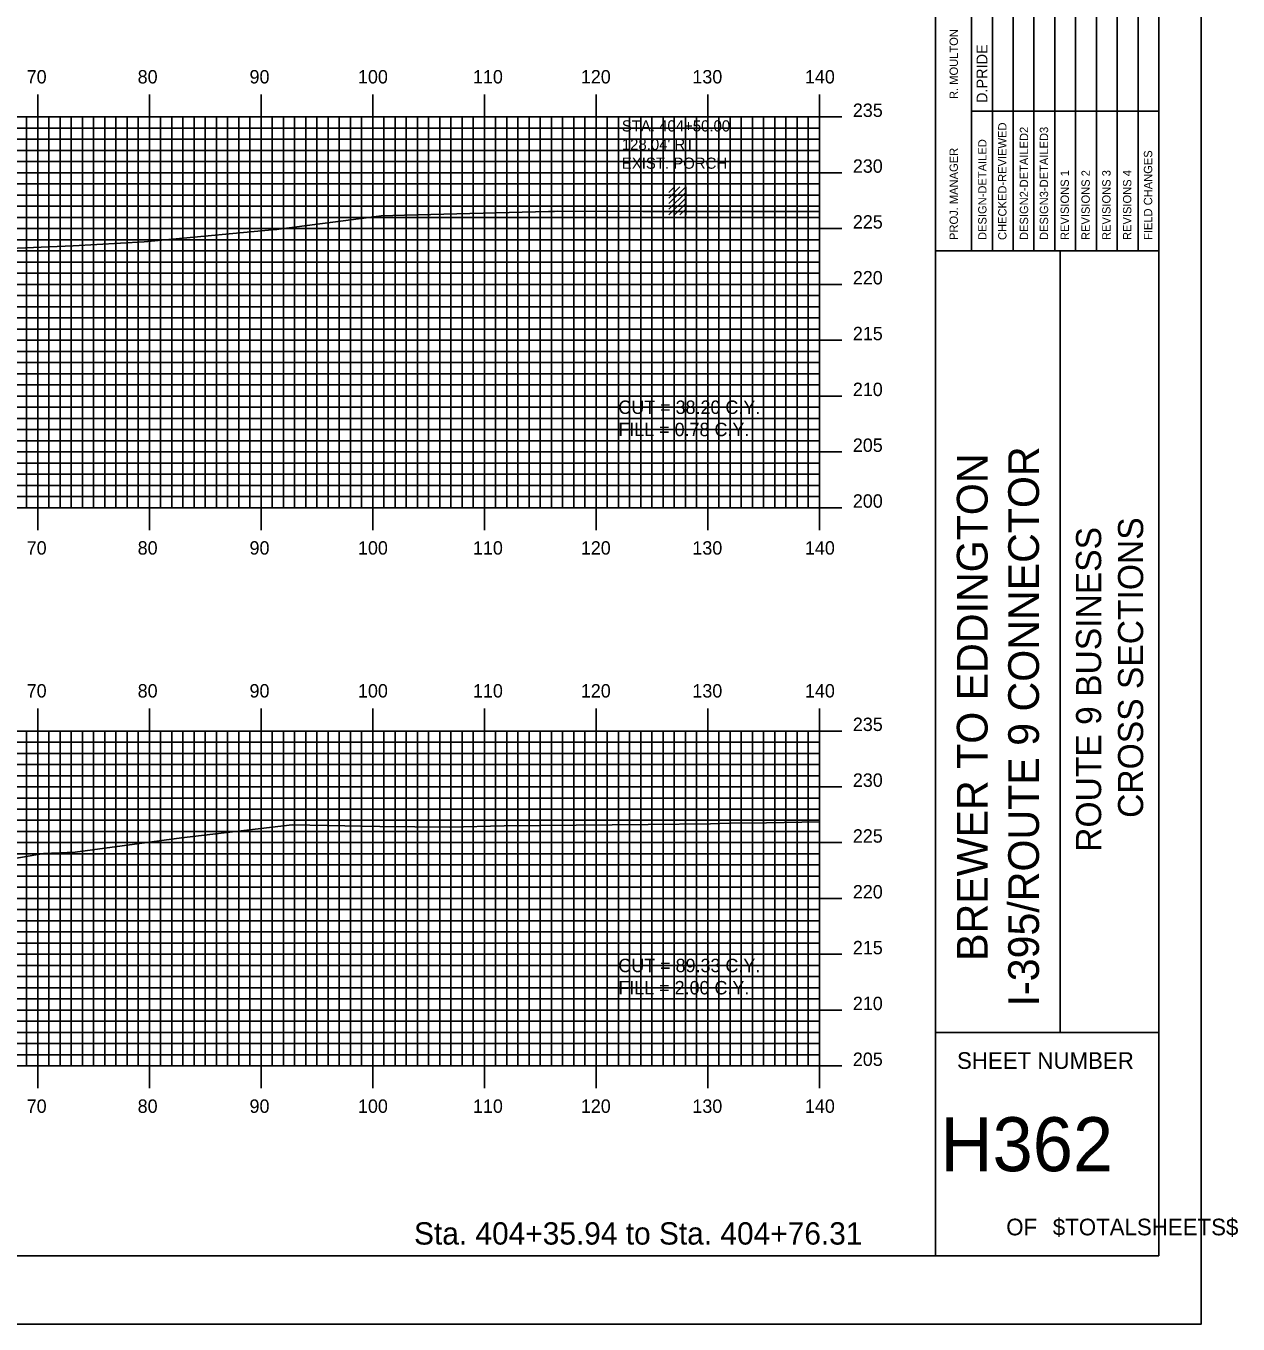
# Model space of a CAD drawing. Extents: x 851348 to 851692, y 364785 to 365005.
# Drawn here: x 851583.1 to 851691.7, y 364785.1 to 364901.4 of the extents above; entities that cross this region are included whole.
import ezdxf

# ---------------------------------------------------------------- set-up
doc = ezdxf.new("R2010")
doc.units = 0
for name, color, linetype in [('BORDER', 7, 'Continuous'), ('D_Text_Monospaced', 7, 'Continuous'), ('D_Text_Standard', 7, 'Continuous'), ('H_V ANNOTATION', 7, 'Continuous'), ('M_Buildings_Attachments', 7, 'Continuous'), ('MAJOR', 7, 'Continuous'), ('MINOR', 7, 'Continuous'), ('PLOT BOUNDARY', 7, 'Continuous'), ('S_Roadway_Centerline', 7, 'Continuous')]:
    doc.layers.add(name, color=color, linetype=linetype)

msp = doc.modelspace()

# ---------------------------------------------------------------- linework, layer by layer
at = {"layer": 'BORDER'}
for p, q in [((851664.59, 364791.23), (851664.59, 365001.23)), ((851664.59, 364881.24), (851684.59, 364881.24)), ((851675.77, 364811.24), (851675.77, 364881.24)), ((851664.59, 364811.24), (851684.59, 364811.24))]:
    msp.add_line(p, q, dxfattribs=at)
msp.add_lwpolyline([(851364.59, 364791.23), (851684.59, 364791.23), (851684.59, 365001.23), (851364.59, 365001.23)], close=True, dxfattribs=at)
for points in [[(851669.69, 364881.24), (851669.69, 364916.24)], [(851671.55, 364916.24), (851671.55, 364881.24)], [(851673.41, 364881.24), (851673.41, 364916.24)], [(851675.28, 364881.24), (851675.28, 364916.24)], [(851677.14, 364881.24), (851677.14, 364916.24)], [(851679, 364881.24), (851679, 364916.24)], [(851680.87, 364881.24), (851680.87, 364916.24)], [(851682.73, 364881.24), (851682.73, 364916.24)], [(851667.82, 364881.24), (851667.82, 364914.83)], [(851667.82, 364893.74), (851684.59, 364893.74)]]:
    msp.add_lwpolyline(points, dxfattribs=at)
at = {"layer": 'M_Buildings_Attachments'}
for p, q in [((851640.72, 364885.47), (851642.23, 364886.98)), ((851640.72, 364885.96), (851641.71, 364886.98)), ((851640.72, 364886.45), (851641.22, 364886.98)), ((851642.23, 364884.45), (851642.23, 364886.98)), ((851640.72, 364884.98), (851642.23, 364886.45)), ((851640.72, 364884.45), (851642.23, 364885.96)), ((851641.22, 364884.45), (851642.23, 364885.47)), ((851641.71, 364884.45), (851642.23, 364884.98))]:
    msp.add_line(p, q, dxfattribs=at)
at = {"layer": 'MAJOR'}
for p, q in [((851584.19, 364895.24), (851584.19, 364893.23)), ((851594.19, 364895.24), (851594.19, 364893.23)), ((851604.19, 364895.24), (851604.19, 364893.23)), ((851614.19, 364895.24), (851614.19, 364893.23)), ((851624.19, 364895.24), (851624.19, 364893.23)), ((851634.19, 364895.24), (851634.19, 364893.23)), ((851644.19, 364895.24), (851644.19, 364893.23)), ((851654.19, 364895.24), (851654.19, 364893.23)), ((851374.19, 364893.23), (851654.19, 364893.23)), ((851374.19, 364893.23), (851654.19, 364893.23)), ((851584.19, 364858.23), (851584.19, 364893.23)), ((851594.19, 364858.23), (851594.19, 364893.23)), ((851604.19, 364858.23), (851604.19, 364893.23)), ((851614.19, 364858.23), (851614.19, 364893.23)), ((851624.19, 364858.23), (851624.19, 364893.23)), ((851634.19, 364858.23), (851634.19, 364893.23)), ((851644.19, 364858.23), (851644.19, 364893.23)), ((851656.2, 364893.23), (851652.19, 364893.23)), ((851654.19, 364858.23), (851654.19, 364893.23)), ((851654.19, 364858.23), (851654.19, 364893.23)), ((851374.19, 364888.23), (851654.19, 364888.23)), ((851656.2, 364888.23), (851652.19, 364888.23)), ((851374.19, 364883.23), (851654.19, 364883.23)), ((851656.2, 364883.23), (851652.19, 364883.23)), ((851374.19, 364878.23), (851654.19, 364878.23)), ((851656.2, 364878.23), (851652.19, 364878.23)), ((851374.19, 364873.23), (851654.19, 364873.23)), ((851656.2, 364873.23), (851652.19, 364873.23)), ((851374.19, 364868.23), (851654.19, 364868.23)), ((851656.2, 364868.23), (851652.19, 364868.23)), ((851374.19, 364863.23), (851654.19, 364863.23)), ((851656.2, 364863.23), (851652.19, 364863.23)), ((851374.19, 364858.23), (851654.19, 364858.23)), ((851374.19, 364858.23), (851654.19, 364858.23)), ((851584.19, 364856.23), (851584.19, 364858.23)), ((851594.19, 364856.23), (851594.19, 364858.23)), ((851604.19, 364856.23), (851604.19, 364858.23)), ((851614.19, 364856.23), (851614.19, 364858.23)), ((851624.19, 364856.23), (851624.19, 364858.23)), ((851634.19, 364856.23), (851634.19, 364858.23)), ((851644.19, 364856.23), (851644.19, 364858.23)), ((851656.2, 364858.23), (851652.19, 364858.23)), ((851654.19, 364856.23), (851654.19, 364858.23)), ((851584.19, 364840.24), (851584.19, 364838.23)), ((851594.19, 364840.24), (851594.19, 364838.23)), ((851604.19, 364840.24), (851604.19, 364838.23)), ((851614.19, 364840.24), (851614.19, 364838.23)), ((851624.19, 364840.24), (851624.19, 364838.23)), ((851634.19, 364840.24), (851634.19, 364838.23)), ((851644.19, 364840.24), (851644.19, 364838.23)), ((851654.19, 364840.24), (851654.19, 364838.23)), ((851374.19, 364838.23), (851654.19, 364838.23)), ((851374.19, 364838.23), (851654.19, 364838.23)), ((851584.19, 364808.23), (851584.19, 364838.23)), ((851594.19, 364808.23), (851594.19, 364838.23)), ((851604.19, 364808.23), (851604.19, 364838.23)), ((851614.19, 364808.23), (851614.19, 364838.23)), ((851624.19, 364808.23), (851624.19, 364838.23)), ((851634.19, 364808.23), (851634.19, 364838.23)), ((851644.19, 364808.23), (851644.19, 364838.23)), ((851656.2, 364838.23), (851652.19, 364838.23)), ((851654.19, 364808.23), (851654.19, 364838.23)), ((851654.19, 364808.23), (851654.19, 364838.23)), ((851374.19, 364833.23), (851654.19, 364833.23)), ((851656.2, 364833.23), (851652.19, 364833.23)), ((851374.19, 364828.23), (851654.19, 364828.23)), ((851656.2, 364828.23), (851652.19, 364828.23)), ((851374.19, 364823.23), (851654.19, 364823.23)), ((851656.2, 364823.23), (851652.19, 364823.23)), ((851374.19, 364818.23), (851654.19, 364818.23)), ((851656.2, 364818.23), (851652.19, 364818.23)), ((851374.19, 364813.23), (851654.19, 364813.23)), ((851656.2, 364813.23), (851652.19, 364813.23)), ((851374.19, 364808.23), (851654.19, 364808.23)), ((851374.19, 364808.23), (851654.19, 364808.23)), ((851584.19, 364806.23), (851584.19, 364808.23)), ((851594.19, 364806.23), (851594.19, 364808.23)), ((851604.19, 364806.23), (851604.19, 364808.23)), ((851614.19, 364806.23), (851614.19, 364808.23)), ((851624.19, 364806.23), (851624.19, 364808.23)), ((851634.19, 364806.23), (851634.19, 364808.23)), ((851644.19, 364806.23), (851644.19, 364808.23)), ((851656.2, 364808.23), (851652.19, 364808.23)), ((851654.19, 364806.23), (851654.19, 364808.23))]:
    msp.add_line(p, q, dxfattribs=at)
at = {"layer": 'MINOR'}
for p, q in [((851583.19, 364858.23), (851583.19, 364893.23)), ((851585.19, 364858.23), (851585.19, 364893.23)), ((851586.19, 364858.23), (851586.19, 364893.23)), ((851587.19, 364858.23), (851587.19, 364893.23)), ((851588.19, 364858.23), (851588.19, 364893.23)), ((851589.19, 364858.23), (851589.19, 364893.23)), ((851590.19, 364858.23), (851590.19, 364893.23)), ((851591.19, 364858.23), (851591.19, 364893.23)), ((851592.19, 364858.23), (851592.19, 364893.23)), ((851593.19, 364858.23), (851593.19, 364893.23)), ((851595.19, 364858.23), (851595.19, 364893.23)), ((851596.19, 364858.23), (851596.19, 364893.23)), ((851597.19, 364858.23), (851597.19, 364893.23)), ((851598.19, 364858.23), (851598.19, 364893.23)), ((851599.19, 364858.23), (851599.19, 364893.23)), ((851600.19, 364858.23), (851600.19, 364893.23)), ((851601.19, 364858.23), (851601.19, 364893.23)), ((851602.19, 364858.23), (851602.19, 364893.23)), ((851603.19, 364858.23), (851603.19, 364893.23)), ((851605.19, 364858.23), (851605.19, 364893.23)), ((851606.19, 364858.23), (851606.19, 364893.23)), ((851607.19, 364858.23), (851607.19, 364893.23)), ((851608.19, 364858.23), (851608.19, 364893.23)), ((851609.19, 364858.23), (851609.19, 364893.23)), ((851610.19, 364858.23), (851610.19, 364893.23)), ((851611.19, 364858.23), (851611.19, 364893.23)), ((851612.19, 364858.23), (851612.19, 364893.23)), ((851613.19, 364858.23), (851613.19, 364893.23)), ((851615.19, 364858.23), (851615.19, 364893.23)), ((851616.19, 364858.23), (851616.19, 364893.23)), ((851617.19, 364858.23), (851617.19, 364893.23)), ((851618.19, 364858.23), (851618.19, 364893.23)), ((851619.19, 364858.23), (851619.19, 364893.23)), ((851620.19, 364858.23), (851620.19, 364893.23)), ((851621.19, 364858.23), (851621.19, 364893.23)), ((851622.19, 364858.23), (851622.19, 364893.23)), ((851623.19, 364858.23), (851623.19, 364893.23)), ((851625.19, 364858.23), (851625.19, 364893.23)), ((851626.19, 364858.23), (851626.19, 364893.23)), ((851627.19, 364858.23), (851627.19, 364893.23)), ((851628.19, 364858.23), (851628.19, 364893.23)), ((851629.19, 364858.23), (851629.19, 364893.23)), ((851630.19, 364858.23), (851630.19, 364893.23)), ((851631.19, 364858.23), (851631.19, 364893.23)), ((851632.19, 364858.23), (851632.19, 364893.23)), ((851633.19, 364858.23), (851633.19, 364893.23)), ((851635.19, 364858.23), (851635.19, 364893.23)), ((851636.19, 364858.23), (851636.19, 364893.23)), ((851637.19, 364858.23), (851637.19, 364893.23)), ((851638.19, 364858.23), (851638.19, 364893.23)), ((851639.19, 364858.23), (851639.19, 364893.23)), ((851640.19, 364858.23), (851640.19, 364893.23)), ((851641.19, 364858.23), (851641.19, 364893.23)), ((851642.19, 364858.23), (851642.19, 364893.23)), ((851643.19, 364858.23), (851643.19, 364893.23)), ((851645.19, 364858.23), (851645.19, 364893.23)), ((851646.19, 364858.23), (851646.19, 364893.23)), ((851647.19, 364858.23), (851647.19, 364893.23)), ((851648.19, 364858.23), (851648.19, 364893.23)), ((851649.19, 364858.23), (851649.19, 364893.23)), ((851650.19, 364858.23), (851650.19, 364893.23)), ((851651.19, 364858.23), (851651.19, 364893.23)), ((851652.19, 364858.23), (851652.19, 364893.23)), ((851653.19, 364858.23), (851653.19, 364893.23)), ((851374.19, 364892.23), (851654.19, 364892.23)), ((851654.19, 364892.23), (851652.19, 364892.23)), ((851374.19, 364891.23), (851654.19, 364891.23)), ((851654.19, 364891.23), (851652.19, 364891.23)), ((851374.19, 364890.23), (851654.19, 364890.23)), ((851654.19, 364890.23), (851652.19, 364890.23)), ((851374.19, 364889.23), (851654.19, 364889.23)), ((851654.19, 364889.23), (851652.19, 364889.23)), ((851374.19, 364887.23), (851654.19, 364887.23)), ((851654.19, 364887.23), (851652.19, 364887.23)), ((851374.19, 364886.23), (851654.19, 364886.23)), ((851654.19, 364886.23), (851652.19, 364886.23)), ((851374.19, 364885.23), (851654.19, 364885.23)), ((851654.19, 364885.23), (851652.19, 364885.23)), ((851374.19, 364884.23), (851654.19, 364884.23)), ((851654.19, 364884.23), (851652.19, 364884.23)), ((851374.19, 364882.23), (851654.19, 364882.23)), ((851374.19, 364881.23), (851654.19, 364881.23)), ((851654.19, 364882.23), (851652.19, 364882.23)), ((851654.19, 364881.23), (851652.19, 364881.23)), ((851374.19, 364880.23), (851654.19, 364880.23)), ((851654.19, 364880.23), (851652.19, 364880.23)), ((851374.19, 364879.23), (851654.19, 364879.23)), ((851654.19, 364879.23), (851652.19, 364879.23)), ((851374.19, 364877.23), (851654.19, 364877.23)), ((851654.19, 364877.23), (851652.19, 364877.23)), ((851374.19, 364876.23), (851654.19, 364876.23)), ((851654.19, 364876.23), (851652.19, 364876.23)), ((851374.19, 364875.23), (851654.19, 364875.23)), ((851374.19, 364874.23), (851654.19, 364874.23)), ((851654.19, 364875.23), (851652.19, 364875.23)), ((851654.19, 364874.23), (851652.19, 364874.23)), ((851374.19, 364872.23), (851654.19, 364872.23)), ((851654.19, 364872.23), (851652.19, 364872.23)), ((851374.19, 364871.23), (851654.19, 364871.23)), ((851654.19, 364871.23), (851652.19, 364871.23)), ((851374.19, 364870.23), (851654.19, 364870.23)), ((851654.19, 364870.23), (851652.19, 364870.23)), ((851374.19, 364869.23), (851654.19, 364869.23)), ((851654.19, 364869.23), (851652.19, 364869.23)), ((851374.19, 364867.23), (851654.19, 364867.23)), ((851654.19, 364867.23), (851652.19, 364867.23)), ((851374.19, 364866.23), (851654.19, 364866.23)), ((851654.19, 364866.23), (851652.19, 364866.23)), ((851374.19, 364865.23), (851654.19, 364865.23)), ((851654.19, 364865.23), (851652.19, 364865.23)), ((851374.19, 364864.23), (851654.19, 364864.23)), ((851654.19, 364864.23), (851652.19, 364864.23)), ((851374.19, 364862.23), (851654.19, 364862.23)), ((851654.19, 364862.23), (851652.19, 364862.23)), ((851374.19, 364861.23), (851654.19, 364861.23)), ((851374.19, 364860.23), (851654.19, 364860.23)), ((851654.19, 364861.23), (851652.19, 364861.23)), ((851654.19, 364860.23), (851652.19, 364860.23)), ((851374.19, 364859.23), (851654.19, 364859.23)), ((851654.19, 364859.23), (851652.19, 364859.23)), ((851583.19, 364808.23), (851583.19, 364838.23)), ((851585.19, 364808.23), (851585.19, 364838.23)), ((851586.19, 364808.23), (851586.19, 364838.23)), ((851587.19, 364808.23), (851587.19, 364838.23)), ((851588.19, 364808.23), (851588.19, 364838.23)), ((851589.19, 364808.23), (851589.19, 364838.23)), ((851590.19, 364808.23), (851590.19, 364838.23)), ((851591.19, 364808.23), (851591.19, 364838.23)), ((851592.19, 364808.23), (851592.19, 364838.23)), ((851593.19, 364808.23), (851593.19, 364838.23)), ((851595.19, 364808.23), (851595.19, 364838.23)), ((851596.19, 364808.23), (851596.19, 364838.23)), ((851597.19, 364808.23), (851597.19, 364838.23)), ((851598.19, 364808.23), (851598.19, 364838.23)), ((851599.19, 364808.23), (851599.19, 364838.23)), ((851600.19, 364808.23), (851600.19, 364838.23)), ((851601.19, 364808.23), (851601.19, 364838.23)), ((851602.19, 364808.23), (851602.19, 364838.23)), ((851603.19, 364808.23), (851603.19, 364838.23)), ((851605.19, 364808.23), (851605.19, 364838.23)), ((851606.19, 364808.23), (851606.19, 364838.23)), ((851607.19, 364808.23), (851607.19, 364838.23)), ((851608.19, 364808.23), (851608.19, 364838.23)), ((851609.19, 364808.23), (851609.19, 364838.23)), ((851610.19, 364808.23), (851610.19, 364838.23)), ((851611.19, 364808.23), (851611.19, 364838.23)), ((851612.19, 364808.23), (851612.19, 364838.23)), ((851613.19, 364808.23), (851613.19, 364838.23)), ((851615.19, 364808.23), (851615.19, 364838.23)), ((851616.19, 364808.23), (851616.19, 364838.23)), ((851617.19, 364808.23), (851617.19, 364838.23)), ((851618.19, 364808.23), (851618.19, 364838.23)), ((851619.19, 364808.23), (851619.19, 364838.23)), ((851620.19, 364808.23), (851620.19, 364838.23)), ((851621.19, 364808.23), (851621.19, 364838.23)), ((851622.19, 364808.23), (851622.19, 364838.23)), ((851623.19, 364808.23), (851623.19, 364838.23)), ((851625.19, 364808.23), (851625.19, 364838.23)), ((851626.19, 364808.23), (851626.19, 364838.23)), ((851627.19, 364808.23), (851627.19, 364838.23)), ((851628.19, 364808.23), (851628.19, 364838.23)), ((851629.19, 364808.23), (851629.19, 364838.23)), ((851630.19, 364808.23), (851630.19, 364838.23)), ((851631.19, 364808.23), (851631.19, 364838.23)), ((851632.19, 364808.23), (851632.19, 364838.23)), ((851633.19, 364808.23), (851633.19, 364838.23)), ((851635.19, 364808.23), (851635.19, 364838.23)), ((851636.19, 364808.23), (851636.19, 364838.23)), ((851637.19, 364808.23), (851637.19, 364838.23)), ((851638.19, 364808.23), (851638.19, 364838.23)), ((851639.19, 364808.23), (851639.19, 364838.23)), ((851640.19, 364808.23), (851640.19, 364838.23)), ((851641.19, 364808.23), (851641.19, 364838.23)), ((851642.19, 364808.23), (851642.19, 364838.23)), ((851643.19, 364808.23), (851643.19, 364838.23)), ((851645.19, 364808.23), (851645.19, 364838.23)), ((851646.19, 364808.23), (851646.19, 364838.23)), ((851647.19, 364808.23), (851647.19, 364838.23)), ((851648.19, 364808.23), (851648.19, 364838.23)), ((851649.19, 364808.23), (851649.19, 364838.23)), ((851650.19, 364808.23), (851650.19, 364838.23)), ((851651.19, 364808.23), (851651.19, 364838.23)), ((851652.19, 364808.23), (851652.19, 364838.23)), ((851653.19, 364808.23), (851653.19, 364838.23)), ((851374.19, 364837.23), (851654.19, 364837.23)), ((851654.19, 364837.23), (851652.19, 364837.23)), ((851374.19, 364836.23), (851654.19, 364836.23)), ((851654.19, 364836.23), (851652.19, 364836.23)), ((851374.19, 364835.23), (851654.19, 364835.23)), ((851654.19, 364835.23), (851652.19, 364835.23)), ((851374.19, 364834.23), (851654.19, 364834.23)), ((851654.19, 364834.23), (851652.19, 364834.23)), ((851374.19, 364832.23), (851654.19, 364832.23)), ((851374.19, 364831.23), (851654.19, 364831.23)), ((851654.19, 364832.23), (851652.19, 364832.23)), ((851654.19, 364831.23), (851652.19, 364831.23)), ((851374.19, 364830.23), (851654.19, 364830.23)), ((851654.19, 364830.23), (851652.19, 364830.23)), ((851374.19, 364829.23), (851654.19, 364829.23)), ((851654.19, 364829.23), (851652.19, 364829.23)), ((851374.19, 364827.23), (851654.19, 364827.23)), ((851654.19, 364827.23), (851652.19, 364827.23)), ((851374.19, 364826.23), (851654.19, 364826.23)), ((851654.19, 364826.23), (851652.19, 364826.23)), ((851374.19, 364825.23), (851654.19, 364825.23)), ((851374.19, 364824.23), (851654.19, 364824.23)), ((851654.19, 364825.23), (851652.19, 364825.23)), ((851654.19, 364824.23), (851652.19, 364824.23)), ((851374.19, 364822.23), (851654.19, 364822.23)), ((851654.19, 364822.23), (851652.19, 364822.23)), ((851374.19, 364821.23), (851654.19, 364821.23)), ((851654.19, 364821.23), (851652.19, 364821.23)), ((851374.19, 364820.23), (851654.19, 364820.23)), ((851654.19, 364820.23), (851652.19, 364820.23)), ((851374.19, 364819.23), (851654.19, 364819.23)), ((851654.19, 364819.23), (851652.19, 364819.23)), ((851374.19, 364817.23), (851654.19, 364817.23)), ((851654.19, 364817.23), (851652.19, 364817.23)), ((851374.19, 364816.23), (851654.19, 364816.23)), ((851654.19, 364816.23), (851652.19, 364816.23)), ((851374.19, 364815.23), (851654.19, 364815.23)), ((851654.19, 364815.23), (851652.19, 364815.23)), ((851374.19, 364814.23), (851654.19, 364814.23)), ((851654.19, 364814.23), (851652.19, 364814.23)), ((851374.19, 364812.23), (851654.19, 364812.23)), ((851654.19, 364812.23), (851652.19, 364812.23)), ((851374.19, 364811.23), (851654.19, 364811.23)), ((851374.19, 364810.23), (851654.19, 364810.23)), ((851654.19, 364811.23), (851652.19, 364811.23)), ((851654.19, 364810.23), (851652.19, 364810.23)), ((851374.19, 364809.23), (851654.19, 364809.23)), ((851654.19, 364809.23), (851652.19, 364809.23))]:
    msp.add_line(p, q, dxfattribs=at)
at = {"layer": 'PLOT BOUNDARY'}
msp.add_lwpolyline([(851348.4, 364785.11), (851688.4, 364785.11), (851688.4, 365005.11), (851348.4, 365005.11)], close=True, dxfattribs=at)
at = {"layer": 'S_Roadway_Centerline'}
for points in [[(851580.93, 364881.42), (851587.35, 364881.68), (851593.71, 364882.03), (851595.31, 364882.19), (851605.48, 364883.14), (851605.59, 364883.16), (851605.79, 364883.18), (851613.83, 364884.22), (851614.96, 364884.37), (851617.05, 364884.42), (851629.94, 364884.76), (851630.48, 364884.77), (851630.73, 364884.78), (851638.37, 364884.77), (851654.19, 364884.77)], [(851579.36, 364826.34), (851584.72, 364827.25), (851587.54, 364827.37), (851597.06, 364828.66), (851606.97, 364829.82), (851614.83, 364829.68), (851621.09, 364829.61), (851625.95, 364829.73), (851638.85, 364829.86), (851644.43, 364829.93), (851646.14, 364829.98), (851649.47, 364830.02), (851654.19, 364830.09)]]:
    msp.add_lwpolyline(points, dxfattribs=at)

# ---------------------------------------------------------------- texts
at = {"layer": 'BORDER'}
for s, height, p in [('R. MOULTON', 0.745, (851666.6, 364894.84)), ('D.PRIDE', 0.969, (851669.24, 364894.48)), ('CHECKED-REVIEWED', 0.7455, (851670.95, 364882.21)), ('DESIGN2-DETAILED2', 0.7455, (851672.89, 364882.21)), ('DESIGN3-DETAILED3', 0.7455, (851674.68, 364882.21)), ('PROJ. MANAGER', 0.7455, (851666.6, 364882.21)), ('DESIGN-DETAILED', 0.7455, (851669.16, 364882.21)), ('FIELD CHANGES', 0.7455, (851684, 364882.21)), ('REVISIONS 1', 0.7455, (851676.54, 364882.21)), ('REVISIONS 2', 0.7455, (851678.41, 364882.21)), ('REVISIONS 3', 0.7455, (851680.27, 364882.21)), ('REVISIONS 4', 0.7455, (851682.13, 364882.21)), ('BREWER TO EDDINGTON', 2.7557, (851669.26, 364817.64)), ('I-395/ROUTE 9 CONNECTOR', 2.7557, (851673.86, 364813.56)), ('CROSS SECTIONS', 2.25, (851683.19, 364830.45)), ('ROUTE 9 BUSINESS', 2.25, (851679.43, 364827.41))]:
    msp.add_text(s, height=height, rotation=90, dxfattribs=at).set_placement(p)
for s, height, p in [('SHEET NUMBER', 1.4905, (851666.52, 364807.97)), ('H362', 4.839, (851665.03, 364798.8)), ('OF', 1.491, (851670.93, 364793.06)), ('$TOTALSHEETS$', 1.4905, (851675.1, 364793.06))]:
    msp.add_text(s, height=height, dxfattribs=at).set_placement(p)
at = {"layer": 'D_Text_Monospaced'}
for s, p in [('STA. 404+50.00', (851636.5, 364891.93)), ("128.04' RT.", (851636.5, 364890.27)), ('EXIST. PORCH', (851636.5, 364888.59))]:
    msp.add_text(s, height=1, dxfattribs=at).set_placement(p)
at = {"layer": 'D_Text_Standard'}
for s, p in [('CUT = 38.20 C.Y.', (851636.19, 364866.63)), ('FILL = 0.78 C.Y.', (851636.19, 364864.64)), ('CUT = 89.33 C.Y.', (851636.19, 364816.63)), ('FILL = 2.00 C.Y.', (851636.19, 364814.64))]:
    msp.add_text(s, height=1.2, dxfattribs=at).set_placement(p)
at = {"layer": 'H_V ANNOTATION'}
for s, height, p in [('70', 1.2, (851583.2, 364896.23)), ('80', 1.2, (851593.14, 364896.23)), ('90', 1.2, (851603.16, 364896.23)), ('100', 1.2, (851612.87, 364896.23)), ('110', 1.2, (851623.17, 364896.23)), ('120', 1.2, (851632.83, 364896.23)), ('130', 1.2, (851642.82, 364896.23)), ('140', 1.2, (851652.9, 364896.23)), ('235', 1.2, (851657.19, 364893.23)), ('230', 1.2, (851657.19, 364888.23)), ('225', 1.2, (851657.19, 364883.23)), ('220', 1.2, (851657.19, 364878.23)), ('215', 1.2, (851657.19, 364873.23)), ('210', 1.2, (851657.19, 364868.23)), ('205', 1.2, (851657.19, 364863.23)), ('200', 1.2, (851657.19, 364858.23)), ('70', 1.2, (851583.2, 364854.03)), ('80', 1.2, (851593.14, 364854.03)), ('90', 1.2, (851603.16, 364854.03)), ('100', 1.2, (851612.87, 364854.03)), ('110', 1.2, (851623.17, 364854.03)), ('120', 1.2, (851632.83, 364854.03)), ('130', 1.2, (851642.82, 364854.03)), ('140', 1.2, (851652.9, 364854.03)), ('70', 1.2, (851583.2, 364841.23)), ('80', 1.2, (851593.14, 364841.23)), ('90', 1.2, (851603.16, 364841.23)), ('100', 1.2, (851612.87, 364841.23)), ('110', 1.2, (851623.17, 364841.23)), ('120', 1.2, (851632.83, 364841.23)), ('130', 1.2, (851642.82, 364841.23)), ('140', 1.2, (851652.9, 364841.23)), ('235', 1.2, (851657.19, 364838.23)), ('230', 1.2, (851657.19, 364833.23)), ('225', 1.2, (851657.19, 364828.23)), ('220', 1.2, (851657.19, 364823.23)), ('215', 1.2, (851657.19, 364818.23)), ('210', 1.2, (851657.19, 364813.23)), ('205', 1.2, (851657.19, 364808.23)), ('70', 1.2, (851583.2, 364804.03)), ('80', 1.2, (851593.14, 364804.03)), ('90', 1.2, (851603.16, 364804.03)), ('100', 1.2, (851612.87, 364804.03)), ('110', 1.2, (851623.17, 364804.03)), ('120', 1.2, (851632.83, 364804.03)), ('130', 1.2, (851642.82, 364804.03)), ('140', 1.2, (851652.9, 364804.03)), ('Sta. 404+35.94 to Sta. 404+76.31', 2.0004, (851617.89, 364792.23))]:
    msp.add_text(s, height=height, dxfattribs=at).set_placement(p)

doc.saveas('drawing.dxf')
